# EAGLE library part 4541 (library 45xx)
OSCILLATOR/PROGRAMMABLE TIMER
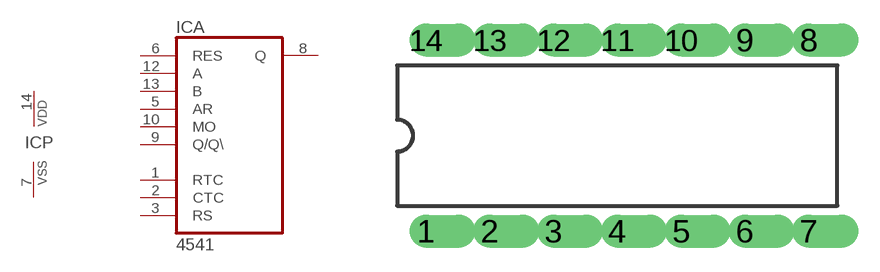
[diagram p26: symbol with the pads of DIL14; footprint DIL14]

Designator prefix IC; gates A=4541 P=PWRN

## 4541N  [DIL14]
1  A:RTC  in
2  A:CTC  in
3  A:RS  in
5  A:AR  in
6  A:RES  in
7  P:VSS  pwr
8  A:Q  out
9  A:Q/Q\  in
10  A:MO  in
12  A:A  in
13  A:B  in
14  P:VDD  pwr

## Footprint DIL14 (pad centres in mm)
Dual In Line
drill 0.813 offset: 1 -7.62,-3.81; 2 -5.08,-3.81; 3 -2.54,-3.81; 4 0,-3.81; 5 2.54,-3.81; 6 5.08,-3.81; 7 7.62,-3.81; 8 7.62,3.81; 9 5.08,3.81; 10 2.54,3.81; 11 0,3.81; 12 -2.54,3.81; 13 -5.08,3.81; 14 -7.62,3.81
